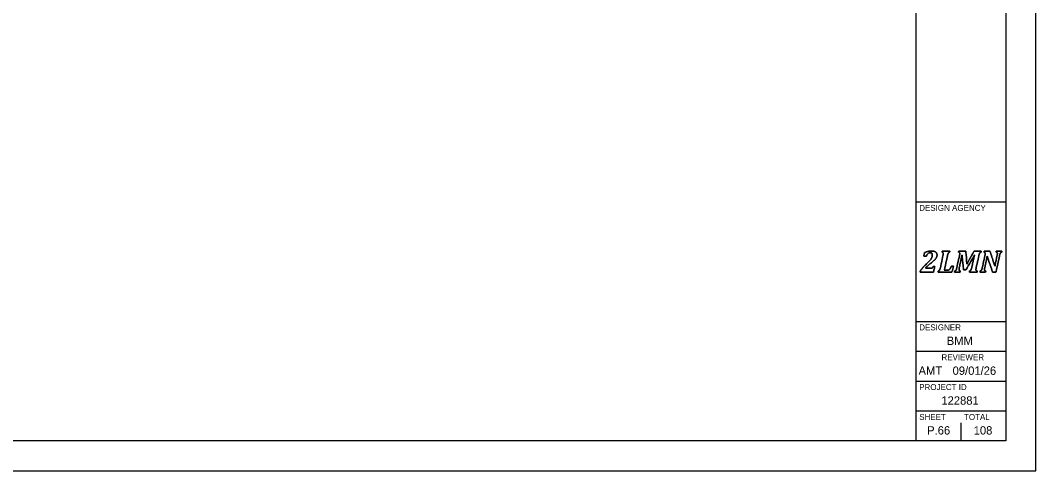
# Model space of a CAD drawing. Extents: x 0 to 34, y 0 to 22.
# Drawn here: x 17 to 34, y 0 to 7.54 of the extents above; entities that cross this region are included whole.
import ezdxf

# ---------------------------------------------------------------- set-up
doc = ezdxf.new("R2010")
doc.units = 0
for name, color, linetype in [('SH_Border', 7, 'Continuous'), ('SH_Cut_Line', 7, 'Continuous'), ('SH_Data', 7, 'Continuous')]:
    doc.layers.add(name, color=color, linetype=linetype)

msp = doc.modelspace()

# ---------------------------------------------------------------- linework, layer by layer
at = {"layer": 'SH_Border'}
for p, q in [((32, 0.5), (32, 21.5)), ((32, 4.5), (33.5, 4.5)), ((32, 2.5), (33.5, 2.5)), ((32, 2), (33.5, 2)), ((32, 1.5), (33.5, 1.5)), ((32, 1), (33.5, 1))]:
    msp.add_line(p, q, dxfattribs=at)
msp.add_lwpolyline([(1.5, 21.5), (33.5, 21.5), (33.5, 0.5), (1.5, 0.5)], close=True, dxfattribs=at)
at = {"layer": 'SH_Cut_Line'}
msp.add_lwpolyline([(0, 0), (34, 0), (34, 22), (0, 22)], close=True, dxfattribs=at)
at = {"layer": 'SH_Data'}
for p, q in [((32.75, 3.5), (32.75, 3.5)), ((32.75, 0.5), (32.75, 0.8)), ((32.375, 0.675), (32.375, 0.675))]:
    msp.add_line(p, q, dxfattribs=at)
for points in [[(32.237, 3.388), (32.246, 3.388), (32.253, 3.389), (32.258, 3.39), (32.263, 3.392), (32.267, 3.394), (32.27, 3.397), (32.273, 3.401), (32.277, 3.408), (32.281, 3.417), (32.281, 3.417), (32.312, 3.417), (32.312, 3.417), (32.312, 3.417), (32.29, 3.326), (32.29, 3.326), (32.29, 3.326), (32.066, 3.326), (32.066, 3.326), (32.066, 3.326), (32.069, 3.343), (32.069, 3.343), (32.078, 3.358), (32.091, 3.375), (32.106, 3.394), (32.122, 3.412), (32.144, 3.435), (32.172, 3.462), (32.197, 3.486), (32.217, 3.506), (32.23, 3.521), (32.243, 3.537), (32.253, 3.551), (32.259, 3.566), (32.266, 3.58), (32.269, 3.595), (32.269, 3.61), (32.269, 3.622), (32.266, 3.632), (32.26, 3.64), (32.253, 3.647), (32.245, 3.65), (32.234, 3.65), (32.22, 3.65), (32.208, 3.646), (32.198, 3.636), (32.188, 3.627), (32.18, 3.613), (32.172, 3.593), (32.172, 3.593), (32.126, 3.593), (32.126, 3.593), (32.126, 3.593), (32.14, 3.654), (32.14, 3.654), (32.166, 3.663), (32.188, 3.669), (32.205, 3.673), (32.223, 3.676), (32.24, 3.678), (32.258, 3.678), (32.278, 3.678), (32.295, 3.675), (32.309, 3.669), (32.322, 3.664), (32.332, 3.656), (32.339, 3.646), (32.345, 3.637), (32.348, 3.626), (32.348, 3.613), (32.348, 3.602), (32.346, 3.591), (32.342, 3.581), (32.339, 3.571), (32.333, 3.56), (32.324, 3.549), (32.315, 3.539), (32.304, 3.526), (32.289, 3.513), (32.275, 3.499), (32.254, 3.482), (32.228, 3.46), (32.216, 3.45), (32.202, 3.438), (32.188, 3.425), (32.174, 3.412), (32.162, 3.4), (32.154, 3.391), (32.154, 3.391), (32.153, 3.388), (32.153, 3.388), (32.153, 3.388), (32.237, 3.388), (32.237, 3.388)], [(32.237, 3.388), (32.237, 3.388), (32.153, 3.388), (32.153, 3.388), (32.153, 3.388), (32.154, 3.391), (32.154, 3.391), (32.162, 3.4), (32.174, 3.412), (32.188, 3.425), (32.202, 3.438), (32.216, 3.45), (32.228, 3.46), (32.254, 3.482), (32.275, 3.499), (32.289, 3.513), (32.304, 3.526), (32.315, 3.539), (32.324, 3.549), (32.333, 3.56), (32.339, 3.571), (32.342, 3.581), (32.346, 3.591), (32.348, 3.602), (32.348, 3.613), (32.348, 3.626), (32.345, 3.637), (32.339, 3.646), (32.332, 3.656), (32.322, 3.664), (32.309, 3.669), (32.295, 3.675), (32.278, 3.678), (32.258, 3.678), (32.24, 3.678), (32.223, 3.676), (32.205, 3.673), (32.188, 3.669), (32.166, 3.663), (32.14, 3.654), (32.14, 3.654), (32.126, 3.593), (32.126, 3.593), (32.126, 3.593), (32.172, 3.593), (32.172, 3.593), (32.18, 3.613), (32.188, 3.627), (32.198, 3.636), (32.208, 3.646), (32.22, 3.65), (32.234, 3.65), (32.245, 3.65), (32.253, 3.647), (32.26, 3.64), (32.266, 3.632), (32.269, 3.622), (32.269, 3.61), (32.269, 3.595), (32.266, 3.58), (32.259, 3.566), (32.253, 3.551), (32.243, 3.537), (32.23, 3.521), (32.217, 3.506), (32.197, 3.486), (32.172, 3.462), (32.144, 3.435), (32.122, 3.412), (32.106, 3.394), (32.091, 3.375), (32.078, 3.358), (32.069, 3.343), (32.069, 3.343), (32.066, 3.326), (32.066, 3.326), (32.066, 3.326), (32.29, 3.326), (32.29, 3.326), (32.29, 3.326), (32.312, 3.417), (32.312, 3.417), (32.312, 3.417), (32.281, 3.417), (32.281, 3.417), (32.277, 3.408), (32.273, 3.401), (32.27, 3.397), (32.267, 3.394), (32.263, 3.392), (32.258, 3.39), (32.253, 3.389), (32.246, 3.388), (32.237, 3.388)], [(32.518, 3.356), (32.527, 3.356), (32.533, 3.357), (32.538, 3.358), (32.542, 3.36), (32.546, 3.362), (32.55, 3.365), (32.554, 3.368), (32.558, 3.372), (32.562, 3.377), (32.567, 3.382), (32.571, 3.388), (32.576, 3.397), (32.58, 3.405), (32.585, 3.415), (32.589, 3.427), (32.589, 3.427), (32.624, 3.427), (32.624, 3.427), (32.624, 3.427), (32.598, 3.326), (32.598, 3.326), (32.598, 3.326), (32.365, 3.326), (32.365, 3.326), (32.365, 3.326), (32.369, 3.343), (32.369, 3.343), (32.376, 3.345), (32.381, 3.348), (32.385, 3.351), (32.389, 3.355), (32.392, 3.36), (32.395, 3.366), (32.398, 3.373), (32.4, 3.382), (32.403, 3.395), (32.403, 3.395), (32.449, 3.605), (32.449, 3.605), (32.452, 3.615), (32.453, 3.625), (32.453, 3.635), (32.453, 3.642), (32.451, 3.647), (32.448, 3.651), (32.444, 3.654), (32.439, 3.656), (32.432, 3.657), (32.432, 3.657), (32.435, 3.674), (32.435, 3.674), (32.435, 3.674), (32.563, 3.674), (32.563, 3.674), (32.563, 3.674), (32.559, 3.657), (32.559, 3.657), (32.552, 3.655), (32.547, 3.652), (32.543, 3.649), (32.539, 3.645), (32.536, 3.64), (32.533, 3.634), (32.531, 3.627), (32.528, 3.618), (32.525, 3.605), (32.525, 3.605), (32.47, 3.356), (32.47, 3.356), (32.47, 3.356), (32.518, 3.356), (32.518, 3.356)], [(32.518, 3.356), (32.518, 3.356), (32.47, 3.356), (32.47, 3.356), (32.47, 3.356), (32.525, 3.605), (32.525, 3.605), (32.528, 3.618), (32.531, 3.627), (32.533, 3.634), (32.536, 3.64), (32.539, 3.645), (32.543, 3.649), (32.547, 3.652), (32.552, 3.655), (32.559, 3.657), (32.559, 3.657), (32.563, 3.674), (32.563, 3.674), (32.563, 3.674), (32.435, 3.674), (32.435, 3.674), (32.435, 3.674), (32.432, 3.657), (32.432, 3.657), (32.439, 3.656), (32.444, 3.654), (32.448, 3.651), (32.451, 3.647), (32.453, 3.642), (32.453, 3.635), (32.453, 3.625), (32.452, 3.615), (32.449, 3.605), (32.449, 3.605), (32.403, 3.395), (32.403, 3.395), (32.4, 3.382), (32.398, 3.373), (32.395, 3.366), (32.392, 3.36), (32.389, 3.355), (32.385, 3.351), (32.381, 3.348), (32.376, 3.345), (32.369, 3.343), (32.369, 3.343), (32.365, 3.326), (32.365, 3.326), (32.365, 3.326), (32.598, 3.326), (32.598, 3.326), (32.598, 3.326), (32.624, 3.427), (32.624, 3.427), (32.624, 3.427), (32.589, 3.427), (32.589, 3.427), (32.585, 3.415), (32.58, 3.405), (32.576, 3.397), (32.571, 3.388), (32.567, 3.382), (32.562, 3.377), (32.558, 3.372), (32.554, 3.368), (32.55, 3.365), (32.546, 3.362), (32.542, 3.36), (32.538, 3.358), (32.533, 3.357), (32.527, 3.356), (32.518, 3.356)], [(32.829, 3.674), (32.829, 3.674), (32.849, 3.461), (32.849, 3.461), (32.849, 3.461), (32.969, 3.674), (32.969, 3.674), (32.969, 3.674), (33.087, 3.674), (33.087, 3.674), (33.087, 3.674), (33.084, 3.657), (33.084, 3.657), (33.077, 3.655), (33.071, 3.652), (33.067, 3.649), (33.064, 3.645), (33.06, 3.64), (33.058, 3.634), (33.055, 3.627), (33.052, 3.618), (33.05, 3.605), (33.05, 3.605), (33.003, 3.395), (33.003, 3.395), (33.002, 3.39), (33.002, 3.387), (33.001, 3.384), (33.001, 3.382), (33.001, 3.379), (33, 3.376), (33, 3.373), (33, 3.369), (33, 3.365), (33, 3.358), (33.002, 3.353), (33.005, 3.349), (33.008, 3.346), (33.014, 3.344), (33.021, 3.343), (33.021, 3.343), (33.018, 3.326), (33.018, 3.326), (33.018, 3.326), (32.89, 3.326), (32.89, 3.326), (32.89, 3.326), (32.893, 3.343), (32.893, 3.343), (32.9, 3.345), (32.906, 3.348), (32.91, 3.351), (32.914, 3.355), (32.917, 3.36), (32.919, 3.366), (32.922, 3.373), (32.925, 3.382), (32.928, 3.395), (32.928, 3.395), (32.951, 3.502), (32.951, 3.502), (32.954, 3.513), (32.957, 3.529), (32.962, 3.548), (32.967, 3.568), (32.972, 3.588), (32.978, 3.609), (32.978, 3.609), (32.973, 3.609), (32.973, 3.609), (32.965, 3.594), (32.957, 3.579), (32.948, 3.563), (32.948, 3.563), (32.833, 3.364), (32.833, 3.364), (32.833, 3.364), (32.792, 3.364), (32.792, 3.364), (32.792, 3.364), (32.775, 3.518), (32.775, 3.518), (32.773, 3.537), (32.772, 3.554), (32.77, 3.569), (32.769, 3.583), (32.768, 3.597), (32.768, 3.611), (32.768, 3.611), (32.764, 3.611), (32.764, 3.611), (32.761, 3.596), (32.758, 3.578), (32.755, 3.558), (32.751, 3.538), (32.747, 3.521), (32.744, 3.507), (32.744, 3.507), (32.72, 3.395), (32.72, 3.395), (32.719, 3.39), (32.718, 3.387), (32.718, 3.384), (32.717, 3.382), (32.717, 3.379), (32.717, 3.376), (32.717, 3.373), (32.716, 3.369), (32.716, 3.365), (32.716, 3.358), (32.718, 3.353), (32.721, 3.349), (32.725, 3.346), (32.73, 3.344), (32.738, 3.343), (32.738, 3.343), (32.734, 3.326), (32.734, 3.326), (32.734, 3.326), (32.641, 3.326), (32.641, 3.326), (32.641, 3.326), (32.644, 3.343), (32.644, 3.343), (32.651, 3.345), (32.657, 3.348), (32.661, 3.351), (32.665, 3.355), (32.668, 3.36), (32.67, 3.366), (32.673, 3.373), (32.676, 3.382), (32.679, 3.395), (32.679, 3.395), (32.725, 3.605), (32.725, 3.605), (32.727, 3.615), (32.728, 3.625), (32.728, 3.635), (32.728, 3.642), (32.727, 3.647), (32.723, 3.651), (32.72, 3.654), (32.715, 3.656), (32.707, 3.657), (32.707, 3.657), (32.711, 3.674), (32.711, 3.674), (32.711, 3.674), (32.829, 3.674), (32.829, 3.674)], [(32.829, 3.674), (32.829, 3.674), (32.711, 3.674), (32.711, 3.674), (32.711, 3.674), (32.707, 3.657), (32.707, 3.657), (32.715, 3.656), (32.72, 3.654), (32.723, 3.651), (32.727, 3.647), (32.728, 3.642), (32.728, 3.635), (32.728, 3.625), (32.727, 3.615), (32.725, 3.605), (32.725, 3.605), (32.679, 3.395), (32.679, 3.395), (32.676, 3.382), (32.673, 3.373), (32.67, 3.366), (32.668, 3.36), (32.665, 3.355), (32.661, 3.351), (32.657, 3.348), (32.651, 3.345), (32.644, 3.343), (32.644, 3.343), (32.641, 3.326), (32.641, 3.326), (32.641, 3.326), (32.734, 3.326), (32.734, 3.326), (32.734, 3.326), (32.738, 3.343), (32.738, 3.343), (32.73, 3.344), (32.725, 3.346), (32.721, 3.349), (32.718, 3.353), (32.716, 3.358), (32.716, 3.365), (32.716, 3.369), (32.717, 3.373), (32.717, 3.376), (32.717, 3.379), (32.717, 3.382), (32.718, 3.384), (32.718, 3.387), (32.719, 3.39), (32.72, 3.395), (32.72, 3.395), (32.744, 3.507), (32.744, 3.507), (32.747, 3.521), (32.751, 3.538), (32.755, 3.558), (32.758, 3.578), (32.761, 3.596), (32.764, 3.611), (32.764, 3.611), (32.768, 3.611), (32.768, 3.611), (32.768, 3.597), (32.769, 3.583), (32.77, 3.569), (32.772, 3.554), (32.773, 3.537), (32.775, 3.518), (32.775, 3.518), (32.792, 3.364), (32.792, 3.364), (32.792, 3.364), (32.833, 3.364), (32.833, 3.364), (32.833, 3.364), (32.948, 3.563), (32.948, 3.563), (32.957, 3.579), (32.965, 3.594), (32.973, 3.609), (32.973, 3.609), (32.978, 3.609), (32.978, 3.609), (32.972, 3.588), (32.967, 3.568), (32.962, 3.548), (32.957, 3.529), (32.954, 3.513), (32.951, 3.502), (32.951, 3.502), (32.928, 3.395), (32.928, 3.395), (32.925, 3.382), (32.922, 3.373), (32.919, 3.366), (32.917, 3.36), (32.914, 3.355), (32.91, 3.351), (32.906, 3.348), (32.9, 3.345), (32.893, 3.343), (32.893, 3.343), (32.89, 3.326), (32.89, 3.326), (32.89, 3.326), (33.018, 3.326), (33.018, 3.326), (33.018, 3.326), (33.021, 3.343), (33.021, 3.343), (33.014, 3.344), (33.008, 3.346), (33.005, 3.349), (33.002, 3.353), (33, 3.358), (33, 3.365), (33, 3.369), (33, 3.373), (33, 3.376), (33.001, 3.379), (33.001, 3.382), (33.001, 3.384), (33.002, 3.387), (33.002, 3.39), (33.003, 3.395), (33.003, 3.395), (33.05, 3.605), (33.05, 3.605), (33.052, 3.618), (33.055, 3.627), (33.058, 3.634), (33.06, 3.64), (33.064, 3.645), (33.067, 3.649), (33.071, 3.652), (33.077, 3.655), (33.084, 3.657), (33.084, 3.657), (33.087, 3.674), (33.087, 3.674), (33.087, 3.674), (32.969, 3.674), (32.969, 3.674), (32.969, 3.674), (32.849, 3.461), (32.849, 3.461), (32.849, 3.461), (32.829, 3.674), (32.829, 3.674)], [(33.137, 3.674), (33.137, 3.674), (33.234, 3.674), (33.234, 3.674), (33.234, 3.674), (33.283, 3.53), (33.283, 3.53), (33.296, 3.49), (33.307, 3.456), (33.315, 3.426), (33.315, 3.426), (33.318, 3.426), (33.318, 3.426), (33.323, 3.455), (33.329, 3.488), (33.337, 3.523), (33.337, 3.523), (33.355, 3.605), (33.355, 3.605), (33.357, 3.615), (33.358, 3.625), (33.358, 3.635), (33.358, 3.642), (33.357, 3.647), (33.353, 3.651), (33.35, 3.654), (33.345, 3.656), (33.337, 3.657), (33.337, 3.657), (33.341, 3.674), (33.341, 3.674), (33.341, 3.674), (33.434, 3.674), (33.434, 3.674), (33.434, 3.674), (33.431, 3.657), (33.431, 3.657), (33.424, 3.655), (33.418, 3.652), (33.414, 3.649), (33.41, 3.645), (33.407, 3.64), (33.405, 3.634), (33.402, 3.627), (33.399, 3.618), (33.396, 3.605), (33.396, 3.605), (33.335, 3.326), (33.335, 3.326), (33.335, 3.326), (33.277, 3.326), (33.277, 3.326), (33.277, 3.326), (33.216, 3.504), (33.216, 3.504), (33.211, 3.518), (33.207, 3.531), (33.204, 3.543), (33.2, 3.556), (33.195, 3.571), (33.19, 3.59), (33.19, 3.59), (33.186, 3.59), (33.186, 3.59), (33.185, 3.579), (33.182, 3.563), (33.179, 3.543), (33.175, 3.523), (33.17, 3.501), (33.165, 3.478), (33.165, 3.478), (33.147, 3.395), (33.147, 3.395), (33.146, 3.39), (33.145, 3.387), (33.145, 3.384), (33.144, 3.382), (33.144, 3.379), (33.144, 3.376), (33.143, 3.373), (33.143, 3.369), (33.143, 3.365), (33.143, 3.358), (33.145, 3.353), (33.148, 3.349), (33.152, 3.346), (33.157, 3.344), (33.164, 3.343), (33.164, 3.343), (33.161, 3.326), (33.161, 3.326), (33.161, 3.326), (33.067, 3.326), (33.067, 3.326), (33.067, 3.326), (33.071, 3.343), (33.071, 3.343), (33.078, 3.345), (33.083, 3.348), (33.087, 3.351), (33.091, 3.355), (33.094, 3.36), (33.097, 3.366), (33.1, 3.373), (33.102, 3.382), (33.105, 3.395), (33.105, 3.395), (33.151, 3.605), (33.151, 3.605), (33.154, 3.615), (33.155, 3.625), (33.155, 3.635), (33.155, 3.642), (33.153, 3.647), (33.15, 3.651), (33.146, 3.654), (33.141, 3.656), (33.134, 3.657), (33.134, 3.657), (33.137, 3.674), (33.137, 3.674)], [(33.137, 3.674), (33.137, 3.674), (33.134, 3.657), (33.134, 3.657), (33.141, 3.656), (33.146, 3.654), (33.15, 3.651), (33.153, 3.647), (33.155, 3.642), (33.155, 3.635), (33.155, 3.625), (33.154, 3.615), (33.151, 3.605), (33.151, 3.605), (33.105, 3.395), (33.105, 3.395), (33.102, 3.382), (33.1, 3.373), (33.097, 3.366), (33.094, 3.36), (33.091, 3.355), (33.087, 3.351), (33.083, 3.348), (33.078, 3.345), (33.071, 3.343), (33.071, 3.343), (33.067, 3.326), (33.067, 3.326), (33.067, 3.326), (33.161, 3.326), (33.161, 3.326), (33.161, 3.326), (33.164, 3.343), (33.164, 3.343), (33.157, 3.344), (33.152, 3.346), (33.148, 3.349), (33.145, 3.353), (33.143, 3.358), (33.143, 3.365), (33.143, 3.369), (33.143, 3.373), (33.144, 3.376), (33.144, 3.379), (33.144, 3.382), (33.145, 3.384), (33.145, 3.387), (33.146, 3.39), (33.147, 3.395), (33.147, 3.395), (33.165, 3.478), (33.165, 3.478), (33.17, 3.501), (33.175, 3.523), (33.179, 3.543), (33.182, 3.563), (33.185, 3.579), (33.186, 3.59), (33.186, 3.59), (33.19, 3.59), (33.19, 3.59), (33.195, 3.571), (33.2, 3.556), (33.204, 3.543), (33.207, 3.531), (33.211, 3.518), (33.216, 3.504), (33.216, 3.504), (33.277, 3.326), (33.277, 3.326), (33.277, 3.326), (33.335, 3.326), (33.335, 3.326), (33.335, 3.326), (33.396, 3.605), (33.396, 3.605), (33.399, 3.618), (33.402, 3.627), (33.405, 3.634), (33.407, 3.64), (33.41, 3.645), (33.414, 3.649), (33.418, 3.652), (33.424, 3.655), (33.431, 3.657), (33.431, 3.657), (33.434, 3.674), (33.434, 3.674), (33.434, 3.674), (33.341, 3.674), (33.341, 3.674), (33.341, 3.674), (33.337, 3.657), (33.337, 3.657), (33.345, 3.656), (33.35, 3.654), (33.353, 3.651), (33.357, 3.647), (33.358, 3.642), (33.358, 3.635), (33.358, 3.625), (33.357, 3.615), (33.355, 3.605), (33.355, 3.605), (33.337, 3.523), (33.337, 3.523), (33.329, 3.488), (33.323, 3.455), (33.318, 3.426), (33.318, 3.426), (33.315, 3.426), (33.315, 3.426), (33.307, 3.456), (33.296, 3.49), (33.283, 3.53), (33.283, 3.53), (33.234, 3.674), (33.234, 3.674), (33.234, 3.674), (33.137, 3.674), (33.137, 3.674)]]:
    msp.add_open_spline(points, degree=3, dxfattribs=at)

# ---------------------------------------------------------------- texts
for s, height, p in [('DESIGN AGENCY', 0.1, (32.05, 4.35)), ('DESIGNER', 0.1, (32.05, 2.35)), ('BMM', 0.14, (32.511, 2.105)), ('REVIEWER', 0.1, (32.422, 1.85)), ('AMT', 0.14, (32.039, 1.605)), ('09/01/26', 0.14, (32.609, 1.605)), ('PROJECT ID', 0.1, (32.05, 1.35)), ('122881', 0.14, (32.421, 1.105)), ('SHEET', 0.1, (32.05, 0.85)), ('TOTAL', 0.1, (32.8, 0.85)), ('P.66', 0.14, (32.183, 0.605)), ('108', 0.14, (32.962, 0.605))]:
    msp.add_text(s, height=height, dxfattribs=at).set_placement(p)

doc.saveas('drawing.dxf')
